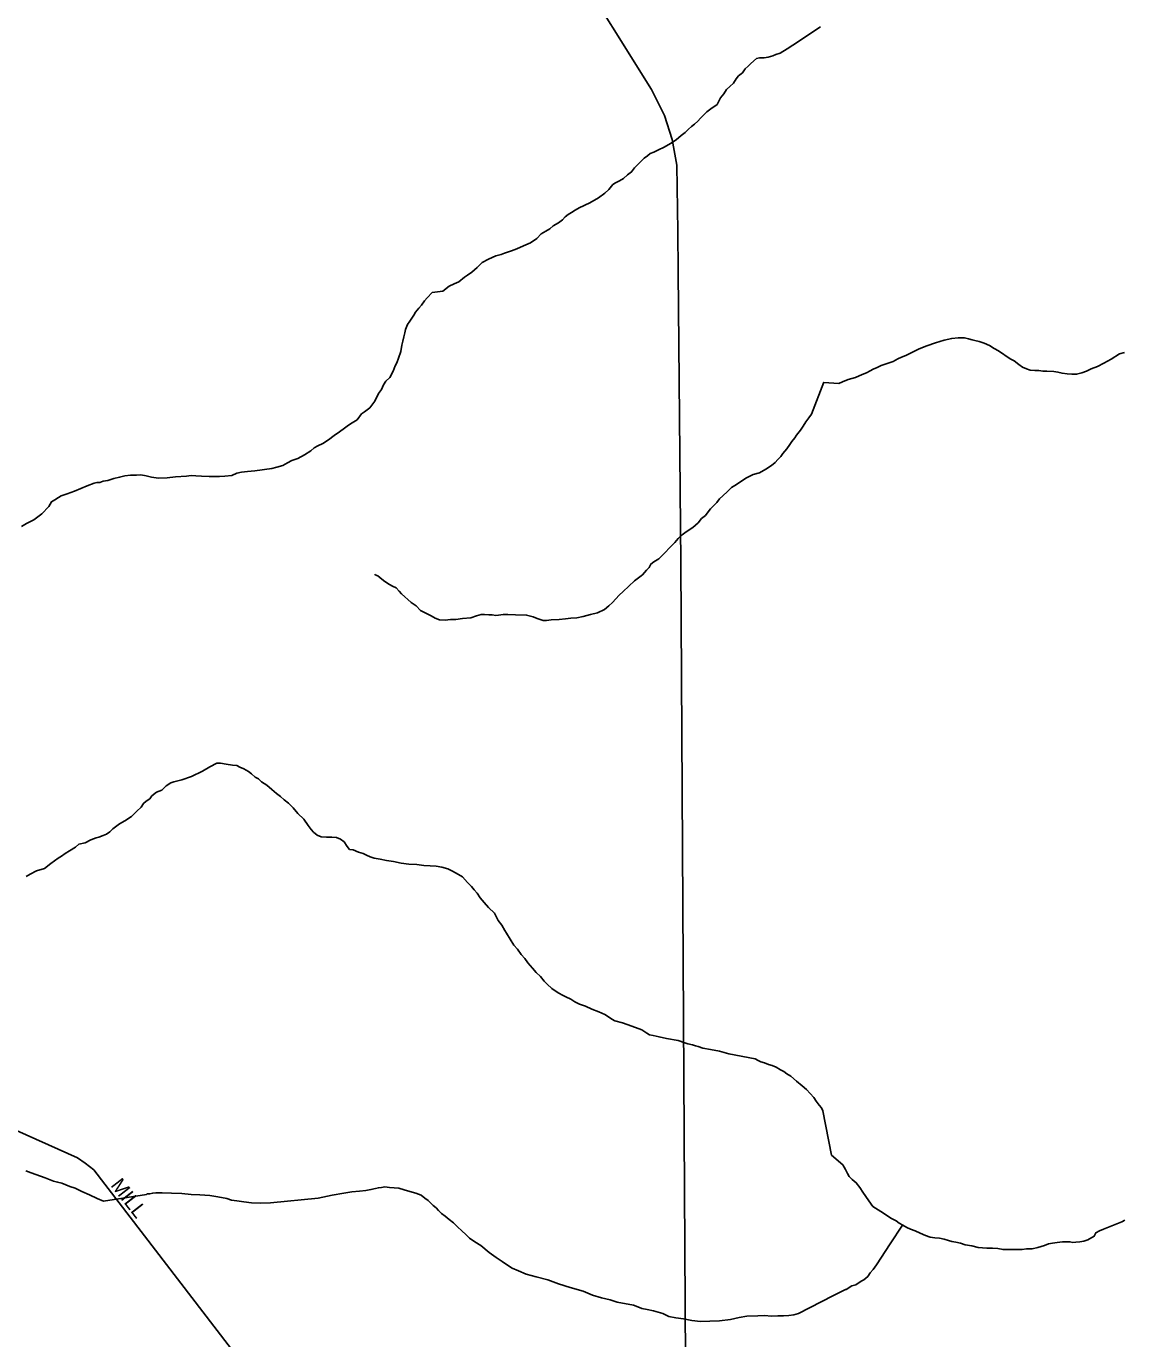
# Model space of a CAD drawing. Extents: x 2010165 to 2382125, y 1060529 to 1407316.
# Drawn here: x 2206176 to 2209958, y 1213095 to 1217618 of the extents above; entities that cross this region are included whole.
import ezdxf

# ---------------------------------------------------------------- set-up
doc = ezdxf.new("R2010")
doc.units = 0
for name, color, linetype in [('GM_X_City_Street', 7, 'Continuous'), ('GM_X_City_Street_Text', 7, 'Continuous'), ('GM_X_Minor_River', 7, 'Continuous'), ('GM_X_State_Route', 7, 'Continuous')]:
    doc.layers.add(name, color=color, linetype=linetype)

msp = doc.modelspace()

# ---------------------------------------------------------------- linework, layer by layer
at = {"layer": 'GM_X_City_Street'}
msp.add_lwpolyline([(2208456.6, 1211503.7), (2207822.4, 1211855.1), (2207786.6, 1211884.3), (2207748.6, 1211924.5), (2207247.8, 1212584.4), (2206408.8, 1213676.7), (2206379.3, 1213700.3), (2206352.7, 1213718), (2205831, 1213951.2), (2204601.3, 1214502.8), (2204508.6, 1214550.1), (2204421.7, 1214605.1), (2204416.3, 1214608.5)], dxfattribs=at)
at = {"layer": 'GM_X_Minor_River'}
for points in [[(2208912.6, 1217616.6), (2208817.8, 1217552.4), (2208798.1, 1217539.8), (2208774.4, 1217525.1), (2208758.5, 1217520.7), (2208748.5, 1217516.4), (2208732.6, 1217512), (2208718.6, 1217509.6), (2208702.6, 1217509.2), (2208692.7, 1217506.9), (2208673, 1217490.3), (2208663.3, 1217480), (2208653.5, 1217471.8), (2208643.9, 1217457.4), (2208630.1, 1217447), (2208622.4, 1217436.8), (2208612.7, 1217422.5), (2208601, 1217410.1), (2208589.3, 1217399.8), (2208579.6, 1217385.5), (2208568, 1217371.1), (2208556.5, 1217348.7), (2208534.9, 1217334.1), (2208521.1, 1217323.7), (2208509.4, 1217311.3), (2208499.7, 1217301.1), (2208489.9, 1217290.8), (2208478.2, 1217280.4), (2208468.4, 1217272.1), (2208458.6, 1217263.8), (2208446.9, 1217251.5), (2208433.1, 1217241.1), (2208415.5, 1217226.6), (2208395.7, 1217214), (2208374, 1217201.4), (2208354.2, 1217192.8), (2208338.4, 1217184.4), (2208326.5, 1217180.1), (2208316.7, 1217171.8), (2208304.9, 1217163.4), (2208271.7, 1217130.4), (2208262, 1217116.1), (2208248.3, 1217105.7), (2208234.6, 1217093.3), (2208220.7, 1217084.9), (2208206.9, 1217078.5), (2208197, 1217072.2), (2208183.4, 1217055.8), (2208169.7, 1217043.4), (2208148.1, 1217026.8), (2208118.5, 1217009.9), (2208080.8, 1216992.9), (2208067, 1216984.5), (2208055.2, 1216976.1), (2208043.4, 1216969.8), (2208033.6, 1216961.5), (2208023.8, 1216951.2), (2208010.1, 1216940.8), (2207992.3, 1216930.3), (2207980.5, 1216920), (2207966.7, 1216911.6), (2207950.9, 1216903.1), (2207935.3, 1216886.7), (2207913.6, 1216872), (2207889.9, 1216861.4), (2207866.1, 1216850.7), (2207848.2, 1216844.2), (2207834.3, 1216839.8), (2207824.4, 1216835.6), (2207812.5, 1216831.2), (2207794.5, 1216826.8), (2207768.8, 1216816), (2207747.1, 1216803.4), (2207729.4, 1216786.9), (2207711.8, 1216770.4), (2207696.1, 1216759.9), (2207686.2, 1216753.6), (2207666.6, 1216737.1), (2207650.8, 1216730.6), (2207632.9, 1216722.1), (2207611.3, 1216705.5), (2207575.4, 1216700.5), (2207557.8, 1216682), (2207548.1, 1216671.7), (2207538.4, 1216657.4), (2207528.7, 1216647.1), (2207517, 1216632.7), (2207511.3, 1216622.5), (2207497.8, 1216602.1), (2207490.1, 1216589.8), (2207482.5, 1216573.6), (2207480.8, 1216561.5), (2207477.2, 1216547.3), (2207473.6, 1216533.2), (2207470, 1216519.1), (2207466.5, 1216496.9), (2207459.1, 1216474.6), (2207453.5, 1216458.4)], [(2209960.6, 1216493.5), (2209942.6, 1216489.3), (2209914.8, 1216470.8), (2209889, 1216456.5), (2209867.1, 1216446.1), (2209845.1, 1216437.8), (2209829.2, 1216429.6), (2209813.3, 1216423.4), (2209795.3, 1216419.1), (2209779.3, 1216418.9), (2209763.2, 1216420.7), (2209745.2, 1216422.5), (2209731.1, 1216426.3), (2209717, 1216428.2), (2209693, 1216429.9), (2209678.9, 1216429.7), (2209664.9, 1216431.5), (2209650.9, 1216431.3), (2209634.8, 1216433.1), (2209622.7, 1216437), (2209608.6, 1216442.8), (2209596.5, 1216452.7), (2209580.3, 1216464.6), (2209566.2, 1216472.4), (2209525.7, 1216500), (2209511.6, 1216507.9), (2209495.5, 1216517.7), (2209477.3, 1216525.5), (2209459.2, 1216531.3), (2209445.1, 1216535.1), (2209435.1, 1216537), (2209423, 1216540.9), (2209408.9, 1216544.7), (2209386.9, 1216544.4), (2209364.9, 1216542.1), (2209338.9, 1216535.8), (2209309, 1216527.4), (2209279.1, 1216516.9), (2209253.2, 1216506.6), (2209227.3, 1216494.2), (2209207.4, 1216483.9), (2209191.4, 1216477.7), (2209179.5, 1216471.5), (2209163.6, 1216463.3), (2209139.6, 1216454.9), (2209121.7, 1216448.7), (2209107.7, 1216442.5), (2209093.8, 1216436.3), (2209083.8, 1216430.1), (2209071.9, 1216423.9), (2209056, 1216417.7), (2209034, 1216407.4), (2209008.1, 1216401), (2208988.1, 1216392.7), (2208976.2, 1216386.6), (2208924.5, 1216390.2)], [(2207453.5, 1216458.4), (2207447.8, 1216448.2), (2207440.3, 1216429.9), (2207428.8, 1216407.5), (2207415.1, 1216395.1), (2207407.5, 1216382.9), (2207399.9, 1216366.6), (2207390.2, 1216352.3), (2207376.9, 1216325.9), (2207359.5, 1216303.3), (2207341.8, 1216288.8), (2207331.9, 1216282.5), (2207316.5, 1216262), (2207298.7, 1216251.5), (2207286.9, 1216243.2), (2207273.1, 1216232.8), (2207255.4, 1216220.3), (2207237.7, 1216207.7), (2207218.1, 1216193.2), (2207198.3, 1216180.6), (2207180.5, 1216172.1), (2207168.7, 1216165.8), (2207156.9, 1216155.4), (2207135.2, 1216140.8), (2207111.5, 1216128.1), (2207091.6, 1216121.6), (2207075.8, 1216113.1), (2207060, 1216104.7), (2207040.1, 1216098.1), (2207022.2, 1216093.7), (2206964.3, 1216086.1), (2206938.3, 1216083.4), (2206918.3, 1216080.9), (2206902.3, 1216078.5), (2206884.5, 1216070), (2206860.5, 1216067.3), (2206842.5, 1216066.9), (2206826.4, 1216066.4), (2206806.4, 1216065.9), (2206780.3, 1216067.2), (2206760.2, 1216068.7), (2206744.1, 1216070.3), (2206728.1, 1216067.9), (2206690.1, 1216064.9), (2206662.1, 1216062.1), (2206632, 1216061.3), (2206607.9, 1216064.7), (2206589.7, 1216068.3), (2206571.6, 1216071.8), (2206555.6, 1216071.4), (2206535.5, 1216070.8), (2206515.6, 1216068.3), (2206497.6, 1216063.8), (2206477.7, 1216059.3), (2206457.8, 1216052.8), (2206441.8, 1216050.3), (2206429.9, 1216046), (2206419.9, 1216045.7), (2206409.9, 1216043.5), (2206386.1, 1216034.8), (2206342.5, 1216015.6), (2206316.7, 1216006.9), (2206296.8, 1216000.3), (2206286.9, 1215994.1), (2206275.1, 1215985.7), (2206263.3, 1215979.4), (2206253.7, 1215963.1), (2206230.3, 1215938.3), (2206202.8, 1215917.6), (2206177.1, 1215904.8), (2206159.3, 1215894.3)], [(2208924.5, 1216391), (2208882.1, 1216281), (2208872.4, 1216268.7), (2208862.8, 1216254.4), (2208853.1, 1216240.1), (2208843.5, 1216225.8), (2208829.9, 1216209.4), (2208824.1, 1216199.2), (2208814.4, 1216186.9), (2208806.7, 1216176.6), (2208797.1, 1216162.3), (2208783.5, 1216145.9), (2208775.7, 1216135.7), (2208766, 1216125.4), (2208756.2, 1216115.1), (2208744.5, 1216104.7), (2208724.8, 1216092.2), (2208703, 1216079.6), (2208681.2, 1216072.9), (2208657.4, 1216062.3), (2208641.6, 1216051.8), (2208623.9, 1216039.3), (2208606.1, 1216028.8), (2208592.5, 1216014.4), (2208576.8, 1215999.9), (2208565.1, 1215989.6), (2208555.4, 1215977.3), (2208543.7, 1215964.9), (2208533.9, 1215954.6), (2208526.2, 1215944.4), (2208516.5, 1215932.1), (2208502.7, 1215921.7), (2208491.1, 1215907.3), (2208473.5, 1215890.8), (2208449.8, 1215876.1), (2208436.1, 1215865.7), (2208422.4, 1215853.3), (2208410.7, 1215839), (2208395.1, 1215822.5), (2208375.6, 1215801.9), (2208356.1, 1215783.3), (2208338.3, 1215772.8), (2208328.5, 1215764.5), (2208322.8, 1215752.3), (2208313, 1215744), (2208299.4, 1215727.6), (2208285.7, 1215717.2), (2208271.9, 1215706.8), (2208232.8, 1215669.6), (2208219.1, 1215657.2), (2208207.4, 1215644.9), (2208195.7, 1215632.5), (2208184, 1215620.2), (2208168.3, 1215607.7), (2208144.5, 1215597.1), (2208120.6, 1215590.4), (2208094.7, 1215583.7), (2208072.8, 1215579.1), (2208052.8, 1215578.6), (2208034.8, 1215576.1), (2208012.8, 1215573.5), (2207984.8, 1215572.8), (2207968.8, 1215570.4), (2207956.8, 1215570), (2207936.5, 1215577.5), (2207922.3, 1215583.2), (2207900.1, 1215588.6), (2207862, 1215589.6), (2207835.9, 1215591), (2207819.8, 1215590.5), (2207803.9, 1215588.1), (2207793.8, 1215587.8), (2207781.8, 1215589.5), (2207769.7, 1215589.2), (2207755.7, 1215590.9), (2207743.6, 1215590.6), (2207727.7, 1215586.1), (2207707.8, 1215579.6), (2207679.8, 1215576.8), (2207655.8, 1215574.2), (2207637.8, 1215573.7), (2207619.8, 1215571.2), (2207599.7, 1215572.7), (2207585.5, 1215578.4), (2207571.3, 1215586), (2207553, 1215595.6), (2207534.7, 1215605.1), (2207520.2, 1215620.8), (2207501.9, 1215632.4), (2207469, 1215661.6), (2207460.7, 1215671.5), (2207450.4, 1215683.2), (2207438.2, 1215688.9), (2207428, 1215694.7), (2207411.7, 1215704.3), (2207401.5, 1215712.1), (2207387.1, 1215723.8), (2207379, 1215727.6), (2207376.9, 1215729.5)], [(2207245, 1214822.5), (2207228.9, 1214824.1), (2207210.8, 1214823.6), (2207192.8, 1214825.1), (2207178.6, 1214830.8), (2207166.3, 1214840.5), (2207158, 1214850.3), (2207147.6, 1214864.1), (2207133, 1214885.8), (2207112.4, 1214905.4), (2207095.8, 1214925), (2207079.4, 1214940.6), (2207065, 1214952.3), (2207052.6, 1214964), (2207038.4, 1214973.7), (2207021.9, 1214987.3), (2207005.5, 1215002.9), (2206987.1, 1215014.5), (2206976.8, 1215024.3), (2206964.6, 1215030), (2206952.3, 1215041.7), (2206942.1, 1215049.5), (2206925.8, 1215059.1), (2206911.6, 1215064.7), (2206901.4, 1215070.5), (2206887.3, 1215072.1), (2206865.2, 1215075.6), (2206845, 1215079), (2206833, 1215078.7), (2206809.3, 1215066.1), (2206783.6, 1215051.3), (2206746, 1215032.3), (2206712.2, 1215021.3), (2206684.3, 1215014.6), (2206674.4, 1215010.3), (2206658.6, 1214999.9), (2206643, 1214985.4), (2206625.1, 1214978.9), (2206609.4, 1214966.4), (2206601.7, 1214956.2), (2206589.9, 1214947.9), (2206580.1, 1214939.6), (2206572.4, 1214927.3), (2206556.7, 1214912.9), (2206539.2, 1214894.3), (2206515.5, 1214879.7), (2206497.7, 1214869.1), (2206487.9, 1214862.9), (2206474.1, 1214852.5), (2206464.4, 1214842.2), (2206452.6, 1214833.8), (2206440.7, 1214829.5), (2206426.8, 1214823.1), (2206416.8, 1214820.8), (2206398.9, 1214814.3), (2206379.2, 1214803.8), (2206357.3, 1214799.2), (2206345.5, 1214788.9), (2206325.8, 1214776.3), (2206310, 1214767.8), (2206298.2, 1214757.5), (2206286.4, 1214751.2), (2206260.8, 1214732.4), (2206239.2, 1214715.8), (2206211.3, 1214707), (2206189.6, 1214696.4), (2206175.8, 1214688)], [(2208950.3, 1213727.8), (2208920.7, 1213880.6), (2208916.4, 1213890.6), (2208908.2, 1213900.4), (2208897.8, 1213914.2), (2208889.4, 1213926), (2208877, 1213939.7), (2208864.6, 1213953.4), (2208850.2, 1213967.1), (2208829.7, 1213982.6), (2208811.2, 1214000.2), (2208797, 1214007.9), (2208786.7, 1214015.6), (2208774.5, 1214021.4), (2208760.3, 1214031), (2208746.1, 1214036.7), (2208733.9, 1214040.4), (2208719.7, 1214046), (2208707.6, 1214049.7), (2208697.5, 1214053.5), (2208687.3, 1214059.2), (2208596.6, 1214076.9), (2208564.3, 1214086.1), (2208534, 1214091.3), (2208507.8, 1214096.7), (2208491.6, 1214102.3), (2208481.6, 1214104), (2208471.4, 1214107.8), (2208455.3, 1214111.4), (2208445.2, 1214115.1), (2208422.9, 1214122.6), (2208382.6, 1214129.5), (2208356.4, 1214134.9), (2208336.2, 1214140.4), (2208324.1, 1214142.1), (2208313.9, 1214147.8), (2208297.6, 1214159.4), (2208263.1, 1214172.6), (2208230.7, 1214183.8), (2208204.5, 1214191.1), (2208194.3, 1214196.9), (2208182.1, 1214204.6), (2208169.8, 1214212.3), (2208149.5, 1214221.8), (2208125.2, 1214231.2), (2208102.9, 1214240.6), (2208082.6, 1214248.1), (2208066.4, 1214255.8), (2208052.1, 1214265.4), (2208035.8, 1214273), (2208023.6, 1214278.7), (2208011.4, 1214286.4), (2207999.2, 1214294.1), (2207986.9, 1214301.9), (2207970.5, 1214317.5), (2207960.2, 1214327.3), (2207947.7, 1214343), (2207933.3, 1214356.7), (2207920.9, 1214372.4), (2207904.3, 1214390.1), (2207893.9, 1214405.8), (2207881.5, 1214419.6), (2207869, 1214437.3), (2207856.6, 1214451), (2207831.4, 1214492.5), (2207825.1, 1214502.4), (2207814.6, 1214520.2), (2207802.1, 1214535.9), (2207789.4, 1214561.7), (2207768.8, 1214581.2), (2207754.3, 1214598.9), (2207739.9, 1214614.6), (2207729.4, 1214630.4), (2207719.1, 1214642.2), (2207710.7, 1214654), (2207696.3, 1214667.7), (2207679.7, 1214687.3), (2207665.5, 1214695), (2207645.1, 1214706.5), (2207628.9, 1214714.1), (2207608.7, 1214719.6), (2207588.6, 1214723.1), (2207568.5, 1214724.6), (2207546.4, 1214726), (2207522.2, 1214729.4), (2207494.1, 1214730.6), (2207467.9, 1214734), (2207441.7, 1214739.3), (2207417.6, 1214742.7), (2207395.4, 1214748.1), (2207375.2, 1214751.6), (2207361.1, 1214755.3), (2207348.9, 1214761), (2207336.7, 1214766.7), (2207320.5, 1214772.3), (2207302.3, 1214779.8), (2207290.2, 1214781.5), (2207281.9, 1214791.3), (2207271.4, 1214807.1), (2207259.2, 1214816.8), (2207245, 1214822.5)], [(2209379.5, 1213428), (2209365.4, 1213429.9), (2209353.3, 1213433.7), (2209339.3, 1213437.6), (2209323.2, 1213441.4), (2209307.1, 1213443.2), (2209291.1, 1213445), (2209275, 1213450.8), (2209256.8, 1213458.6), (2209238.7, 1213466.4), (2209222.6, 1213472.2), (2209210.5, 1213478.1), (2209196.4, 1213485.9), (2209184.2, 1213493.8), (2209174.1, 1213501.7), (2209158, 1213509.5), (2209141.8, 1213519.4), (2209129.7, 1213527.2), (2209093.3, 1213550.9), (2209079.1, 1213570.8), (2209068.9, 1213584.7), (2209058.6, 1213600.6), (2209048.4, 1213616.6), (2209036.2, 1213632.5), (2209022, 1213644.3), (2209011.8, 1213654.2), (2209005.7, 1213664.2), (2208999.5, 1213678.2), (2208989.3, 1213694.1), (2208950.3, 1213727.9)], [(2206590.3, 1213592.6), (2206442.6, 1213568.6), (2206420.3, 1213578.1), (2206393.8, 1213591.4), (2206367.5, 1213602.8), (2206345.1, 1213614.3), (2206326.9, 1213619.8), (2206312.7, 1213625.5), (2206298.5, 1213631.1), (2206284.4, 1213634.8), (2206270.2, 1213638.4), (2206258.1, 1213642.1), (2206241.9, 1213649.7), (2206225.7, 1213655.3), (2206209.5, 1213660.9), (2206193.3, 1213666.5), (2206175, 1213674.1)], [(2208955, 1213243), (2208837.3, 1213181.8), (2208821.4, 1213177.3), (2208803.4, 1213174.8), (2208785.4, 1213174.3), (2208765.3, 1213173.8), (2208743.3, 1213173.3), (2208721.2, 1213174.7), (2208697.1, 1213174.1), (2208659.1, 1213173.1), (2208633.1, 1213168.3), (2208603.2, 1213161.6), (2208565.3, 1213156.5), (2208531.2, 1213155.6), (2208499.1, 1213154.8), (2208469, 1213158), (2208440.8, 1213163.3), (2208414.6, 1213166.6), (2208390.4, 1213172), (2208370.1, 1213181.5), (2208337.7, 1213190.7), (2208315.5, 1213196.2), (2208297.4, 1213199.7), (2208283.2, 1213205.3), (2208269, 1213211), (2208212.6, 1213221.6), (2208188.3, 1213229), (2208158, 1213236.2), (2208127.7, 1213245.4), (2208095.3, 1213258.6), (2208050.8, 1213271.5), (2208010.4, 1213284.5), (2207973.9, 1213297.6), (2207933.5, 1213308.6), (2207899.2, 1213317.7), (2207872.8, 1213329.1), (2207850.5, 1213338.6), (2207834.2, 1213348.2), (2207815.8, 1213361.7), (2207795.3, 1213375.2), (2207770.8, 1213392.7), (2207742.1, 1213416), (2207721.7, 1213429.5), (2207703.3, 1213441.1), (2207690.9, 1213454.8), (2207676.6, 1213466.5), (2207662.2, 1213480.2), (2207647.8, 1213493.9), (2207633.4, 1213505.5), (2207619.1, 1213517.2), (2207606.8, 1213526.9), (2207596.5, 1213536.7), (2207588.2, 1213546.5), (2207578, 1213554.3), (2207561.4, 1213571.9), (2207549.2, 1213579.6), (2207536.9, 1213589.3), (2207518.6, 1213596.9), (2207498.4, 1213602.4), (2207478.3, 1213607.9), (2207460.1, 1213613.4), (2207444, 1213615), (2207427.9, 1213616.6), (2207411.8, 1213618.2), (2207399.8, 1213615.8), (2207389.8, 1213615.6), (2207379.8, 1213613.3), (2207363.9, 1213608.9), (2207345.9, 1213606.4), (2207324, 1213603.8), (2207298, 1213601.1), (2207270, 1213596.4), (2207230.1, 1213589.3), (2207182.2, 1213580), (2207018.2, 1213563.7), (2206982.2, 1213562.7), (2206952, 1213563.9), (2206925.9, 1213567.3), (2206901.7, 1213570.6), (2206883.6, 1213572.2), (2206867.4, 1213577.8), (2206849.3, 1213581.3), (2206829.2, 1213584.8), (2206809, 1213588.3), (2206774.8, 1213591.4), (2206744.7, 1213592.6), (2206712.6, 1213595.8), (2206676.4, 1213596.9), (2206644.3, 1213598), (2206622.3, 1213597.4), (2206612.3, 1213597.2), (2206602.3, 1213594.9), (2206592.3, 1213594.6), (2206590.3, 1213592.6)], [(2209194.9, 1213486.9), (2209153, 1213422)], [(2209961.5, 1213503.7), (2209951.6, 1213497.6), (2209887.8, 1213472.7), (2209873.9, 1213466.5), (2209861.9, 1213460.3), (2209856.1, 1213448.2), (2209834.2, 1213435.8), (2209820.2, 1213431.7), (2209806.2, 1213429.5), (2209792.2, 1213427.3), (2209782.2, 1213427.2), (2209772.2, 1213429), (2209760.2, 1213428.9), (2209746.1, 1213428.7), (2209728.1, 1213426.5), (2209712.1, 1213424.2), (2209698.1, 1213422.1), (2209684.2, 1213415.9), (2209662.2, 1213409.6), (2209642.3, 1213405.3), (2209622.2, 1213405), (2209608.2, 1213402.8), (2209594.2, 1213402.7), (2209578.2, 1213402.5), (2209560.1, 1213402.2), (2209542.1, 1213402), (2209524, 1213405.8), (2209506, 1213407.6), (2209485.9, 1213407.3), (2209455.9, 1213408.9), (2209433.7, 1213414.7), (2209411.6, 1213418.4), (2209395.5, 1213424.2), (2209379.5, 1213428)], [(2209153, 1213422), (2209106, 1213350.2), (2209094.2, 1213334), (2209084.3, 1213321.9), (2209076.5, 1213309.7), (2209062.6, 1213297.5), (2209052.6, 1213293.3), (2209034.7, 1213281.1), (2209020.8, 1213276.9), (2209000.9, 1213264.6), (2208998.9, 1213264.6), (2208955, 1213243)]]:
    msp.add_lwpolyline(points, dxfattribs=at)
at = {"layer": 'GM_X_State_Route'}
for points in [[(2208422.9, 1216772.2), (2208421.8, 1216911.9), (2208418.1, 1217139), (2208402.2, 1217227.5), (2208375.1, 1217311), (2208331, 1217400.6), (2208056, 1217840.3), (2207580.8, 1218597.3), (2207244.4, 1219135.6), (2207112.8, 1219355), (2207042, 1219530.2), (2206989.8, 1219694.1), (2206846.5, 1220420)], [(2208449.9, 1212623.7), (2208431.1, 1215769.2), (2208422.9, 1216772.2)]]:
    msp.add_lwpolyline(points, dxfattribs=at)

# ---------------------------------------------------------------- texts
at = {"layer": 'GM_X_City_Street_Text'}
msp.add_text('MILL', height=50, rotation=307.8744, dxfattribs=at).set_placement((2206464.7, 1213623.4))

doc.saveas('drawing.dxf')
